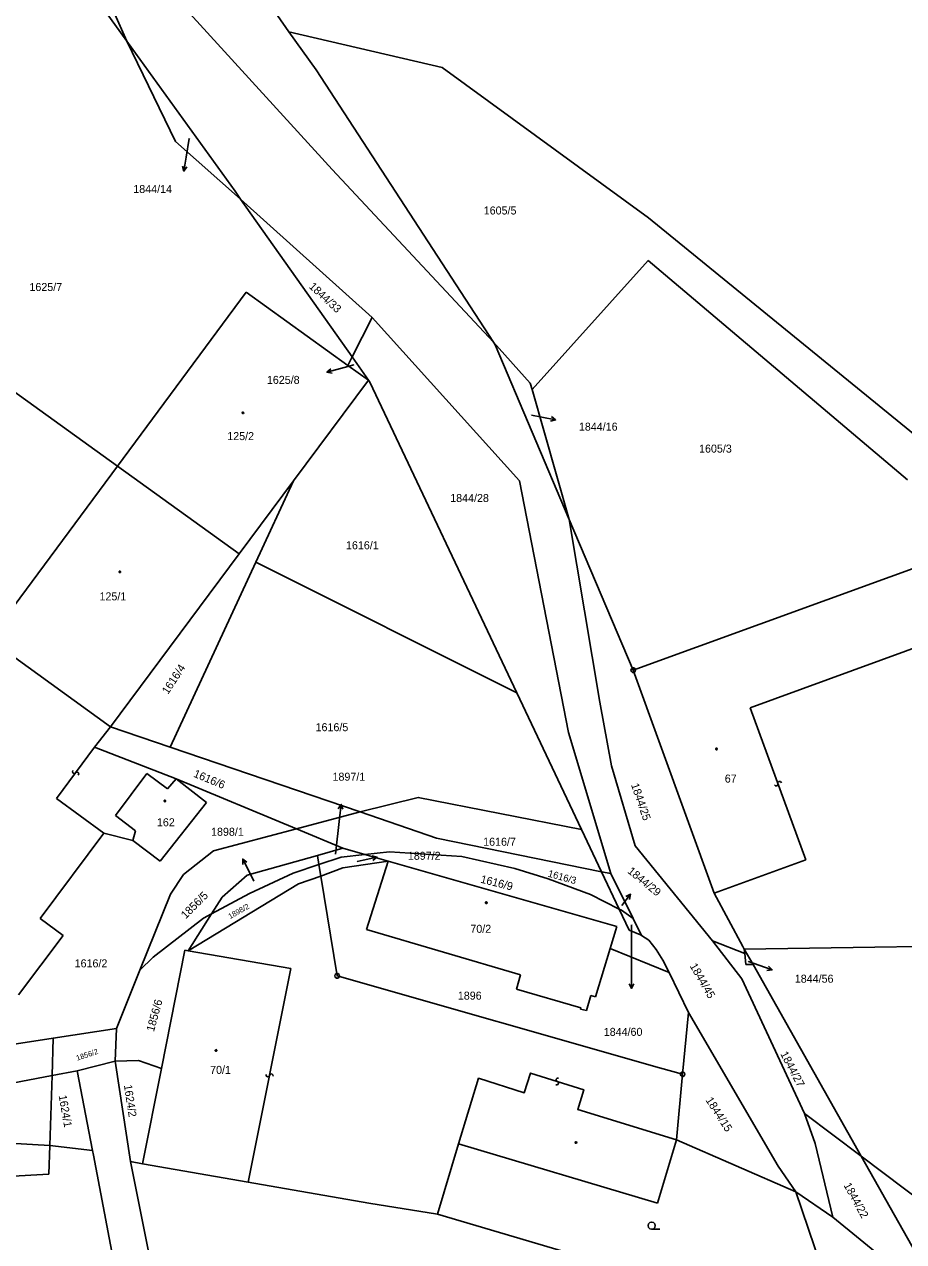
# Model space of a CAD drawing. Extents: x -747792 to -745414, y -1093712 to -1091463.
# Drawn here: x -747123 to -747029.6, y -1092152.8 to -1092023.4 of the extents above; entities that cross this region are included whole.
import ezdxf

# ---------------------------------------------------------------- set-up
doc = ezdxf.new("R2010")
doc.units = 0
for name, color, linetype in [('Pracovní_bod JDTM STC_VC', 7, 'Continuous'), ('Pracovní_bod JDTM STC_VC - výška', 7, 'Continuous'), ('Pracovní_bod JDTM STC_VC - číslo', 7, 'Continuous'), ('Pracovní_bod NN - výška', 7, 'Continuous'), ('Pracovní_bod polohopisu', 7, 'Continuous'), ('Pracovní_bod polohopisu - výška', 7, 'Continuous'), ('Pracovní_bod VN - výška', 7, 'Continuous')]:
    doc.layers.add(name, color=color, linetype=linetype)

msp = doc.modelspace()

# ---------------------------------------------------------------- linework, layer by layer
at = {"layer": 'Pracovní_bod JDTM STC_VC - výška'}
for points in [[(-747099.76, -1092064.61), (-747099.71, -1092064.62), (-747099.69, -1092064.67), (-747099.68, -1092064.7), (-747099.69, -1092064.75), (-747099.73, -1092064.78), (-747099.76, -1092064.78), (-747099.8, -1092064.77), (-747099.83, -1092064.74), (-747099.84, -1092064.7), (-747099.83, -1092064.65), (-747099.79, -1092064.62)], [(-747112.84, -1092081.51), (-747112.79, -1092081.52), (-747112.76, -1092081.56), (-747112.75, -1092081.59), (-747112.76, -1092081.64), (-747112.8, -1092081.67), (-747112.84, -1092081.68), (-747112.89, -1092081.66), (-747112.92, -1092081.63), (-747112.93, -1092081.59), (-747112.92, -1092081.54), (-747112.88, -1092081.51)], [(-747049.48, -1092100.33), (-747049.43, -1092100.34), (-747049.41, -1092100.39), (-747049.4, -1092100.42), (-747049.41, -1092100.46), (-747049.45, -1092100.5), (-747049.48, -1092100.51), (-747049.52, -1092100.49), (-747049.55, -1092100.46), (-747049.57, -1092100.42), (-747049.55, -1092100.38), (-747049.51, -1092100.34)], [(-747108.06, -1092105.84), (-747108.01, -1092105.85), (-747107.99, -1092105.9), (-747107.98, -1092105.93), (-747107.99, -1092105.98), (-747108.03, -1092106.01), (-747108.06, -1092106.02), (-747108.1, -1092106), (-747108.14, -1092105.97), (-747108.15, -1092105.93), (-747108.14, -1092105.88), (-747108.09, -1092105.85)], [(-747073.91, -1092116.66), (-747073.86, -1092116.67), (-747073.83, -1092116.71), (-747073.83, -1092116.74), (-747073.83, -1092116.79), (-747073.88, -1092116.82), (-747073.91, -1092116.82), (-747073.96, -1092116.81), (-747073.99, -1092116.78), (-747074, -1092116.74), (-747073.99, -1092116.69), (-747073.95, -1092116.66)], [(-747102.63, -1092132.35), (-747102.58, -1092132.36), (-747102.55, -1092132.41), (-747102.54, -1092132.44), (-747102.55, -1092132.48), (-747102.59, -1092132.52), (-747102.63, -1092132.52), (-747102.68, -1092132.51), (-747102.71, -1092132.48), (-747102.72, -1092132.44), (-747102.71, -1092132.4), (-747102.67, -1092132.36)], [(-747064.35, -1092142.15), (-747064.31, -1092142.22), (-747064.35, -1092142.29), (-747064.45, -1092142.29), (-747064.49, -1092142.22), (-747064.45, -1092142.15)]]:
    msp.add_lwpolyline(points, close=True, dxfattribs=at)
at = {"layer": 'Pracovní_bod JDTM STC_VC - číslo'}
msp.add_lwpolyline([(-747056.36, -1092151.43), (-747056.55, -1092151.38), (-747056.69, -1092151.24), (-747056.73, -1092151.05), (-747056.69, -1092150.87), (-747056.55, -1092150.73), (-747056.36, -1092150.68), (-747056.17, -1092150.73), (-747056.03, -1092150.87), (-747055.98, -1092151.05), (-747056.03, -1092151.24), (-747056.17, -1092151.38), (-747056.36, -1092151.43), (-747055.48, -1092151.43)], dxfattribs=at)
at = {"layer": 'Pracovní_bod NN - výška'}
for points in [[(-747112.09, -1092025.19), (-747121.59, -1092003.79)], [(-747120.96, -1092012.87), (-747112.09, -1092025.19)], [(-747090.29, -1092038.83), (-747109.48, -1092017.78)], [(-747096.11, -1092022.48), (-747094.89, -1092024.2)], [(-747112.09, -1092025.19), (-747100.6, -1092041.16)], [(-747106.91, -1092035.87), (-747112.09, -1092025.19)], [(-747094.89, -1092024.2), (-747078.6, -1092027.99)], [(-747094.89, -1092024.2), (-747092, -1092028.25)], [(-747073.15, -1092057.2), (-747092, -1092028.25)], [(-747078.6, -1092027.99), (-747056.69, -1092043.98)], [(-747100.02, -1092041.98), (-747106.91, -1092035.87)], [(-747073.15, -1092057.2), (-747090.29, -1092038.83)], [(-747100.02, -1092041.98), (-747100.6, -1092041.16)], [(-747086.04, -1092054.55), (-747100.02, -1092041.98)], [(-747088.16, -1092058.76), (-747100.02, -1092041.98)], [(-747056.69, -1092043.98), (-747026.05, -1092068.95)], [(-747143.72, -1092048.29), (-747113.1, -1092070.36)], [(-747056.72, -1092048.51), (-747069.05, -1092062.2)], [(-747029.19, -1092071.82), (-747056.72, -1092048.51)], [(-747099.43, -1092051.89), (-747113.1, -1092070.36)], [(-747088.62, -1092059.67), (-747099.43, -1092051.89)], [(-747086.04, -1092054.55), (-747088.16, -1092058.76)], [(-747070.38, -1092071.92), (-747086.04, -1092054.55)], [(-747072.97, -1092057.48), (-747073.15, -1092057.2)], [(-747073.15, -1092057.2), (-747069.24, -1092061.54)], [(-747065.1, -1092076.02), (-747072.97, -1092057.48)], [(-747088.16, -1092058.76), (-747088.62, -1092059.67)], [(-747086.44, -1092061.24), (-747088.16, -1092058.76)], [(-747086.44, -1092061.24), (-747088.62, -1092059.67)], [(-747094.39, -1092071.92), (-747086.44, -1092061.24)], [(-747086.27, -1092061.44), (-747086.44, -1092061.24)], [(-747070.66, -1092094.44), (-747086.27, -1092061.44)], [(-747069.24, -1092061.54), (-747069.05, -1092062.2)], [(-747069.05, -1092062.2), (-747065.1, -1092076.02)], [(-747113.1, -1092070.36), (-747126.72, -1092088.75)], [(-747100.17, -1092079.68), (-747113.1, -1092070.36)], [(-747100.17, -1092079.68), (-747094.39, -1092071.92)], [(-747098.4, -1092080.56), (-747094.39, -1092071.92)], [(-747070.38, -1092071.92), (-747065.2, -1092098.66)], [(-747065.1, -1092076.02), (-747061.85, -1092095.42)], [(-747058.31, -1092092.03), (-747065.1, -1092076.02)], [(-747113.84, -1092098.04), (-747100.17, -1092079.68)], [(-747058.31, -1092092.03), (-747024.29, -1092079.66)], [(-747107.51, -1092100.2), (-747098.4, -1092080.56)], [(-747098.4, -1092080.56), (-747070.66, -1092094.44)], [(-747113.84, -1092098.04), (-747126.47, -1092088.92)], [(-747058.31, -1092092.03), (-747049.7, -1092115.73)], [(-747070.66, -1092094.44), (-747063.8, -1092108.96)], [(-747061.85, -1092095.42), (-747060.62, -1092102.21)], [(-747115.53, -1092100.2), (-747113.84, -1092098.04)], [(-747107.51, -1092100.2), (-747113.84, -1092098.04)], [(-747065.2, -1092098.66), (-747060.7, -1092113.64)], [(-747115.53, -1092100.2), (-747106.86, -1092103.58)], [(-747107.51, -1092100.2), (-747087.31, -1092107.1)], [(-747060.62, -1092102.21), (-747058.1, -1092110.71)], [(-747109.97, -1092103.02), (-747113.29, -1092107.46)], [(-747107.78, -1092104.66), (-747109.97, -1092103.02)], [(-747106.86, -1092103.58), (-747107.78, -1092104.66)], [(-747103.64, -1092106.08), (-747106.86, -1092103.58)], [(-747094.06, -1092108.9), (-747106.86, -1092103.58)], [(-747087.31, -1092107.1), (-747081.14, -1092105.55), (-747063.8, -1092108.96)], [(-747108.57, -1092112.32), (-747103.64, -1092106.08)], [(-747111.16, -1092109.09), (-747113.29, -1092107.46)], [(-747094.06, -1092108.9), (-747087.31, -1092107.1)], [(-747087.31, -1092107.1), (-747079.19, -1092109.87)], [(-747121.29, -1092118.41), (-747114.54, -1092109.37)], [(-747114.54, -1092109.37), (-747111.45, -1092110.15)], [(-747111.45, -1092110.15), (-747111.16, -1092109.09)], [(-747094.06, -1092108.9), (-747102.89, -1092111.23)], [(-747089.17, -1092110.94), (-747094.06, -1092108.9)], [(-747063.8, -1092108.96), (-747061.67, -1092113.46)], [(-747111.45, -1092110.15), (-747108.57, -1092112.32)], [(-747061.67, -1092113.46), (-747079.19, -1092109.87)], [(-747058.1, -1092110.71), (-747049.89, -1092120.78)], [(-747102.89, -1092111.23), (-747106.06, -1092113.76)], [(-747091.86, -1092111.71), (-747099.32, -1092113.83)], [(-747091.86, -1092111.71), (-747089.17, -1092110.94)], [(-747091.86, -1092111.71), (-747091.7, -1092112.68)], [(-747091.7, -1092112.68), (-747089.34, -1092111.9)], [(-747086.81, -1092111.62), (-747089.34, -1092111.9)], [(-747089.17, -1092110.94), (-747086.81, -1092111.62)], [(-747086.81, -1092111.62), (-747084.19, -1092111.32)], [(-747086.81, -1092111.62), (-747084.35, -1092112.32)], [(-747084.19, -1092111.32), (-747076.51, -1092111.83)], [(-747076.51, -1092111.83), (-747070.89, -1092113.11)], [(-747094.42, -1092113.59), (-747091.7, -1092112.68)], [(-747091.7, -1092112.68), (-747091.49, -1092113.93)], [(-747089.17, -1092113.04), (-747091.49, -1092113.93)], [(-747084.35, -1092112.32), (-747089.17, -1092113.04)], [(-747084.35, -1092112.32), (-747086.64, -1092119.59)], [(-747060.06, -1092119.28), (-747084.35, -1092112.32)], [(-747070.89, -1092113.11), (-747067.35, -1092114.2)], [(-747106.06, -1092113.76), (-747107.46, -1092115.85)], [(-747091.49, -1092113.93), (-747093.88, -1092114.75), (-747105.57, -1092121.85)], [(-747099.32, -1092113.83), (-747101.97, -1092116.14)], [(-747099.07, -1092115.76), (-747094.42, -1092113.59)], [(-747091.49, -1092113.93), (-747089.76, -1092124.52), (-747055.51, -1092134.27), (-747053.07, -1092134.97)], [(-747067.35, -1092114.2), (-747062.86, -1092115.88)], [(-747060.7, -1092113.64), (-747061.67, -1092113.46)], [(-747059.8, -1092117.43), (-747061.67, -1092113.46)], [(-747060.7, -1092113.64), (-747058.32, -1092118.43)], [(-747107.46, -1092115.85), (-747110.71, -1092123.9)], [(-747103.1, -1092117.92), (-747099.07, -1092115.76)], [(-747062.86, -1092115.88), (-747059.8, -1092117.43)], [(-747049.7, -1092115.73), (-747046.68, -1092121.39)], [(-747101.97, -1092116.14), (-747103.1, -1092117.92)], [(-747118.85, -1092120.21), (-747121.29, -1092118.41)], [(-747109.29, -1092122.52), (-747103.95, -1092118.38)], [(-747103.1, -1092117.92), (-747105.57, -1092121.85)], [(-747103.95, -1092118.38), (-747103.1, -1092117.92)], [(-747058.74, -1092119.66), (-747059.8, -1092117.43)], [(-747059.8, -1092117.43), (-747059.55, -1092117.55)], [(-747059.55, -1092117.55), (-747058.32, -1092118.43)], [(-747058.32, -1092118.43), (-747057.44, -1092120.21)], [(-747086.64, -1092119.59), (-747070.27, -1092124.4)], [(-747060.06, -1092119.28), (-747060.76, -1092121.6)], [(-747057.53, -1092120.16), (-747058.74, -1092119.66)], [(-747123.61, -1092126.53), (-747118.85, -1092120.21)], [(-747057.44, -1092120.21), (-747057.53, -1092120.16)], [(-747056.65, -1092120.72), (-747057.44, -1092120.21)], [(-747055.87, -1092121.7), (-747056.65, -1092120.72)], [(-747049.89, -1092120.78), (-747046.77, -1092124.82)], [(-747049.89, -1092120.78), (-747046.47, -1092122.14)], [(-747108.43, -1092134.36), (-747105.94, -1092121.79)], [(-747105.57, -1092121.85), (-747105.94, -1092121.79)], [(-747060.76, -1092121.6), (-747062.31, -1092126.74)], [(-747054.51, -1092124.15), (-747060.76, -1092121.6)], [(-747055.15, -1092122.84), (-747055.87, -1092121.7)], [(-747046.52, -1092121.67), (-747046.68, -1092121.39)], [(-747014.14, -1092121.19), (-747046.52, -1092121.67)], [(-747046.47, -1092122.14), (-747046.52, -1092121.67)], [(-747046.52, -1092121.67), (-747045.59, -1092123.32)], [(-747046.35, -1092123.32), (-747046.47, -1092122.14)], [(-747110.71, -1092123.9), (-747109.29, -1092122.52)], [(-747054.51, -1092124.15), (-747055.15, -1092122.84)], [(-747046.35, -1092123.32), (-747045.59, -1092123.32)], [(-747034.1, -1092143.66), (-747045.59, -1092123.32)], [(-747110.71, -1092123.9), (-747113.21, -1092130.09)], [(-747070.27, -1092124.4), (-747070.72, -1092125.93)], [(-747052.44, -1092128.4), (-747054.51, -1092124.15)], [(-747040.11, -1092139.14), (-747046.77, -1092124.82)], [(-747070.72, -1092125.93), (-747063.86, -1092127.91)], [(-747063.27, -1092128.19), (-747062.81, -1092126.6)], [(-747062.81, -1092126.6), (-747062.31, -1092126.74)], [(-747063.86, -1092127.91), (-747063.9, -1092128.04)], [(-747063.9, -1092128.04), (-747063.27, -1092128.19)], [(-747052.44, -1092128.4), (-747053.07, -1092134.97)], [(-747042.91, -1092144.73), (-747052.44, -1092128.4)], [(-747119.91, -1092131.12), (-747113.21, -1092130.09)], [(-747113.35, -1092133.56), (-747113.21, -1092130.09)], [(-747132.35, -1092133.04), (-747119.91, -1092131.12)], [(-747120.04, -1092135.1), (-747119.91, -1092131.12)], [(-747113.35, -1092133.56), (-747117.36, -1092134.59)], [(-747110.87, -1092133.5), (-747113.35, -1092133.56)], [(-747113.35, -1092133.56), (-747111.71, -1092144.25)], [(-747108.43, -1092134.36), (-747110.87, -1092133.5)], [(-747160.16, -1092142.79), (-747120.04, -1092135.1)], [(-747120.04, -1092135.1), (-747120.28, -1092142.53)], [(-747120.04, -1092135.1), (-747117.36, -1092134.59)], [(-747117.36, -1092134.59), (-747115.74, -1092143.08)], [(-747110.43, -1092144.47), (-747108.43, -1092134.36)], [(-747053.07, -1092134.97), (-747053.73, -1092141.95)], [(-747040.11, -1092139.14), (-747034.1, -1092143.66)], [(-747038.98, -1092142.32), (-747040.11, -1092139.14)], [(-747120.28, -1092142.53), (-747142.32, -1092141.28)], [(-747120.28, -1092142.53), (-747120.38, -1092145.57)], [(-747115.74, -1092143.08), (-747120.28, -1092142.53)], [(-747076.87, -1092142.37), (-747079.09, -1092149.83)], [(-747055.75, -1092148.67), (-747076.87, -1092142.37)], [(-747055.75, -1092148.67), (-747053.73, -1092141.95)], [(-747041.05, -1092147.46), (-747053.73, -1092141.95)], [(-747037.12, -1092150.15), (-747038.98, -1092142.32)], [(-747115.74, -1092143.08), (-747115.65, -1092143.56)], [(-747115.65, -1092143.56), (-747111.77, -1092163.94)], [(-747111.71, -1092144.25), (-747110.43, -1092144.47)], [(-747107.87, -1092163.41), (-747111.71, -1092144.25)], [(-747020.29, -1092154.1), (-747034.1, -1092143.66)], [(-747024.71, -1092160.27), (-747034.1, -1092143.66)], [(-747120.38, -1092145.57), (-747203.28, -1092150.22)], [(-747099.2, -1092146.43), (-747110.43, -1092144.47)], [(-747041.05, -1092147.46), (-747042.91, -1092144.73)], [(-747099.2, -1092146.43), (-747086.39, -1092148.67)], [(-747037.12, -1092150.15), (-747041.05, -1092147.46)], [(-747035.75, -1092163), (-747041.05, -1092147.46)], [(-747086.39, -1092148.67), (-747079.09, -1092149.83)], [(-747079.09, -1092149.83), (-747060.29, -1092155.38)], [(-747024.71, -1092160.27), (-747037.12, -1092150.15)]]:
    msp.add_lwpolyline(points, dxfattribs=at)
at = {"layer": 'Pracovní_bod polohopisu'}
for points in [[(-747045.9, -1092096.02), (-747015.53, -1092084.95)], [(-747039.99, -1092112.18), (-747045.9, -1092096.02)], [(-747119.55, -1092105.68), (-747115.53, -1092100.2)], [(-747117.83, -1092102.7), (-747117.88, -1092102.85), (-747117.79, -1092102.99), (-747117.64, -1092103.01), (-747117.43, -1092102.87), (-747117.28, -1092102.9), (-747117.2, -1092103.05), (-747117.25, -1092103.18)], [(-747043.31, -1092104.21), (-747043.21, -1092104.33), (-747043.04, -1092104.33), (-747042.94, -1092104.22), (-747042.94, -1092103.97), (-747042.83, -1092103.86), (-747042.67, -1092103.88), (-747042.58, -1092103.99)], [(-747119.55, -1092105.68), (-747114.54, -1092109.37)], [(-747049.7, -1092115.73), (-747039.99, -1092112.18)], [(-747105.57, -1092121.85), (-747094.67, -1092123.73)], [(-747099.2, -1092146.43), (-747094.67, -1092123.73)], [(-747097.3, -1092134.98), (-747097.28, -1092135.14), (-747097.14, -1092135.23), (-747096.99, -1092135.19), (-747096.86, -1092134.97), (-747096.71, -1092134.94), (-747096.58, -1092135.03), (-747096.57, -1092135.18)], [(-747053.73, -1092141.95), (-747064.2, -1092138.72), (-747063.57, -1092136.62), (-747069.21, -1092134.84), (-747069.88, -1092136.94), (-747074.74, -1092135.4), (-747076.87, -1092142.37)], [(-747066.53, -1092136.08), (-747066.37, -1092136.08), (-747066.26, -1092135.95), (-747066.29, -1092135.8), (-747066.49, -1092135.64), (-747066.51, -1092135.49), (-747066.4, -1092135.38), (-747066.25, -1092135.38)]]:
    msp.add_lwpolyline(points, dxfattribs=at)
at = {"layer": 'Pracovní_bod polohopisu - výška'}
for points in [[(-747105.49, -1092035.54), (-747105.8, -1092037.53)], [(-747106.03, -1092039.01), (-747105.8, -1092037.53)], [(-747105.71, -1092038.56), (-747106.03, -1092039.01), (-747106.2, -1092038.48)], [(-747090.85, -1092060.38), (-747089.4, -1092059.99)], [(-747090.3, -1092060.49), (-747090.85, -1092060.38), (-747090.43, -1092060.01)], [(-747087.97, -1092059.6), (-747089.4, -1092059.99)], [(-747069.13, -1092064.93), (-747068.02, -1092065.15)], [(-747066.55, -1092065.44), (-747068.02, -1092065.15)], [(-747066.99, -1092065.1), (-747066.55, -1092065.44), (-747067.09, -1092065.59)], [(-747089.64, -1092106.77), (-747089.33, -1092106.3), (-747089.14, -1092106.82)], [(-747089.33, -1092106.3), (-747089.5, -1092107.79)], [(-747089.92, -1092111.57), (-747089.5, -1092107.79)], [(-747085.53, -1092111.9), (-747086.99, -1092112.23)], [(-747086.07, -1092111.76), (-747085.53, -1092111.9), (-747085.96, -1092112.25)], [(-747099.79, -1092112.11), (-747099.1, -1092113.44)], [(-747099.78, -1092112.67), (-747099.79, -1092112.11), (-747099.34, -1092112.44)], [(-747087.63, -1092112.38), (-747086.99, -1092112.23)], [(-747098.59, -1092114.44), (-747099.1, -1092113.44)], [(-747058.6, -1092115.84), (-747059.51, -1092117.03)], [(-747059.1, -1092116.08), (-747058.6, -1092115.84), (-747058.7, -1092116.39)], [(-747058.5, -1092119.11), (-747058.49, -1092124.35)], [(-747046.08, -1092123), (-747044.98, -1092123.39)], [(-747043.57, -1092123.89), (-747044.98, -1092123.39)], [(-747043.95, -1092123.49), (-747043.57, -1092123.89), (-747044.12, -1092123.96)], [(-747058.49, -1092125.85), (-747058.49, -1092124.35)], [(-747058.24, -1092125.35), (-747058.49, -1092125.85), (-747058.74, -1092125.35)]]:
    msp.add_lwpolyline(points, dxfattribs=at)
at = {"layer": 'Pracovní_bod VN - výška'}
for points in [[(-747058.24, -1092091.79), (-747058.11, -1092091.89), (-747058.06, -1092092.03), (-747058.11, -1092092.18), (-747058.24, -1092092.27), (-747058.39, -1092092.27), (-747058.51, -1092092.18), (-747058.56, -1092092.03), (-747058.51, -1092091.89), (-747058.39, -1092091.79)], [(-747089.69, -1092124.28), (-747089.56, -1092124.38), (-747089.51, -1092124.52), (-747089.56, -1092124.67), (-747089.69, -1092124.76), (-747089.83, -1092124.76), (-747089.96, -1092124.67), (-747090.01, -1092124.52), (-747089.96, -1092124.38), (-747089.83, -1092124.28)], [(-747052.99, -1092134.73), (-747052.87, -1092134.82), (-747052.82, -1092134.97), (-747052.87, -1092135.11), (-747052.99, -1092135.21), (-747053.15, -1092135.21), (-747053.27, -1092135.11), (-747053.32, -1092134.97), (-747053.27, -1092134.82), (-747053.15, -1092134.73)]]:
    msp.add_lwpolyline(points, close=True, dxfattribs=at)
for points in [[(-747058.34, -1092092.03), (-747058.29, -1092092.03)], [(-747089.79, -1092124.52), (-747089.73, -1092124.52)], [(-747053.09, -1092134.97), (-747053.04, -1092134.97)]]:
    msp.add_lwpolyline(points, dxfattribs=at)

# ---------------------------------------------------------------- texts
at = {"layer": 'Pracovní_bod JDTM STC_VC'}
for s, height, p in [('1844/14', 0.05, (-747105.61, -1092035.54)), ('1605/5', 0.85, (-747074.19, -1092043.62)), ('1625/7', 0.85, (-747122.44, -1092051.75)), ('1625/8', 0.05, (-747088.09, -1092059.6)), ('1844/16', 0.05, (-747069.25, -1092064.93)), ('125/2', 0.85, (-747101.43, -1092067.59)), ('1605/3', 0.85, (-747051.32, -1092068.92)), ('1844/28', 0.85, (-747077.75, -1092074.17)), ('1616/1', 0.85, (-747088.82, -1092079.19)), ('125/1', 0.85, (-747115, -1092084.62)), ('1616/5', 0.85, (-747092.05, -1092098.52)), ('67', 0.85, (-747048.59, -1092103.98)), ('162', 0.85, (-747108.9, -1092108.62)), ('1616/7', 0.85, (-747074.25, -1092110.69)), ('1897/1', 0.05, (-747089.91, -1092111.5)), ('1897/2', 0.05, (-747087.74, -1092112.38)), ('1898/1', 0.05, (-747098.69, -1092114.44)), ('1844/29', 0.05, (-747059.64, -1092117.03)), ('70/2', 0.85, (-747075.61, -1092119.94)), ('1844/60', 0.05, (-747058.63, -1092119.11)), ('1616/2', 0.85, (-747117.64, -1092123.61)), ('1844/56', 0.05, (-747046.21, -1092123)), ('1896', 0.85, (-747076.94, -1092127.04)), ('70/1', 0.85, (-747103.25, -1092134.93))]:
    msp.add_text(s, height=height, dxfattribs=at).set_placement(p)
for s, height, rotation, p in [('1844/33', 0.85, 317.4186, (-747092.82, -1092051.36)), ('1616/4', 0.85, 56.6655, (-747107.73, -1092094.67)), ('1616/6', 0.85, 337.4721, (-747105.09, -1092103.34)), ('1844/25', 0.85, 289.0572, (-747058.56, -1092104.21)), ('1616/3', 0.75, 344.4049, (-747067.43, -1092113.96)), ('1616/9', 0.85, 345.8373, (-747074.59, -1092114.6)), ('1856/5', 0.85, 44.9772, (-747105.85, -1092118.52)), ('1898/2', 0.57, 29.5073, (-747101.12, -1092118.49)), ('1844/45', 0.85, 300.058, (-747052.34, -1092123.46)), ('1856/6', 0.85, 74.6564, (-747109.22, -1092130.5)), ('1856/2', 0.57, 18.5065, (-747117.37, -1092133.54)), ('1844/27', 0.85, 297.7662, (-747042.72, -1092132.8)), ('1624/2', 0.85, 278.744, (-747112.41, -1092136.13)), ('1624/1', 0.85, 280.0045, (-747119.34, -1092137.24)), ('1844/15', 0.85, 302.7509, (-747050.66, -1092137.72)), ('1844/22', 0.85, 298.7402, (-747035.99, -1092146.76))]:
    msp.add_text(s, height=height, rotation=rotation, dxfattribs=at).set_placement(p)
at = {"layer": 'Pracovní_bod polohopisu - výška'}
for s, p in [('1844/14', (-747111.41, -1092041.34)), ('1625/8', (-747097.22, -1092061.62)), ('1844/16', (-747064.08, -1092066.59)), ('1897/1', (-747090.25, -1092103.78)), ('1898/1', (-747103.15, -1092109.63)), ('1897/2', (-747082.25, -1092112.18)), ('1844/56', (-747041.15, -1092125.24)), ('1844/60', (-747061.44, -1092130.89))]:
    msp.add_text(s, height=0.85, dxfattribs=at).set_placement(p)
msp.add_text('1844/29', height=0.85, rotation=320.6272, dxfattribs=at).set_placement((-747058.98, -1092113.51))

doc.saveas('drawing.dxf')
